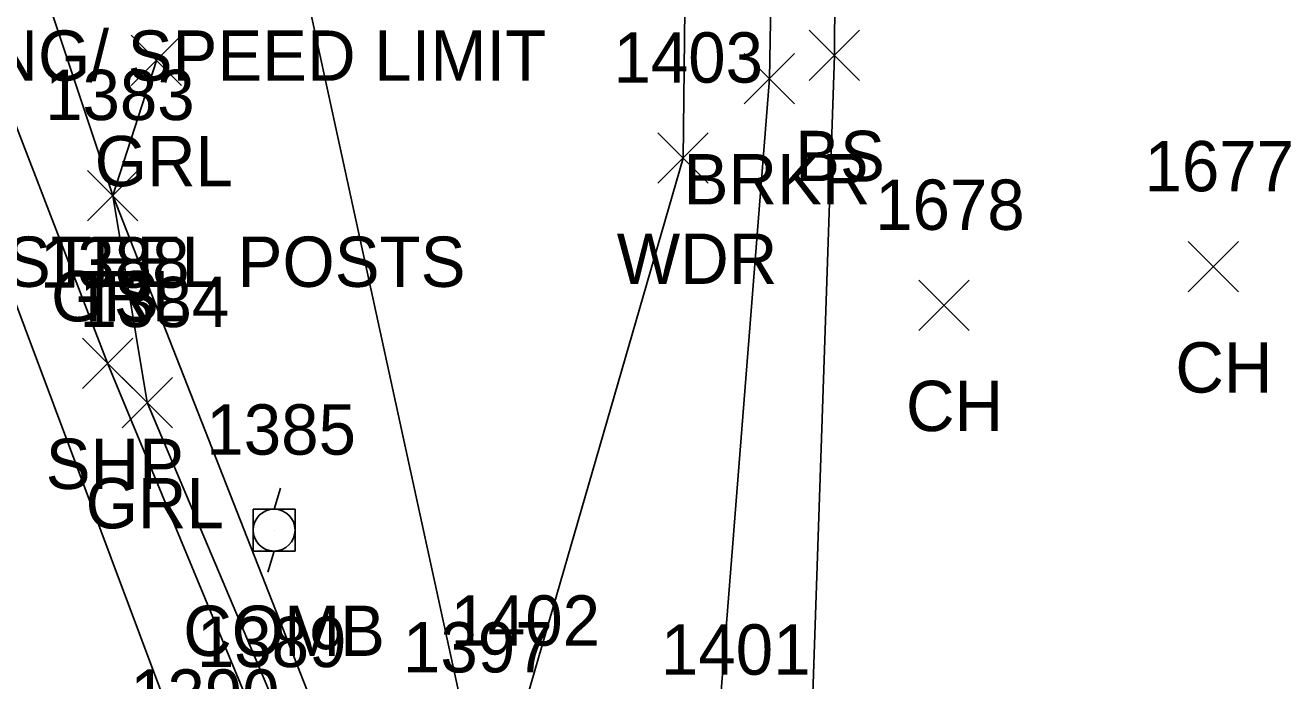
# Model space of a CAD drawing. Extents: x 1651305 to 1654558, y 539481 to 548441.
# Drawn here: x 1654313.4 to 1654363.7, y 544722 to 544748.1 of the extents above; entities that cross this region are included whole.
import ezdxf

# ---------------------------------------------------------------- set-up
doc = ezdxf.new("R2010")
doc.units = 0
for name, color, linetype in [('L_A', 7, 'Continuous'), ('L_I', 7, 'Continuous'), ('L_TIC', 7, 'Continuous'), ('LAWA', 7, 'Continuous'), ('LAWE', 7, 'Continuous'), ('LELB', 7, 'Continuous'), ('P_A', 7, 'Continuous'), ('P_I', 7, 'Continuous'), ('P_TIC', 7, 'Continuous'), ('PET', 7, 'Continuous'), ('PSP', 7, 'Continuous'), ('R_A', 7, 'Continuous'), ('R_C', 7, 'Continuous'), ('R_I', 7, 'Continuous'), ('R_TIC', 7, 'Continuous'), ('RGR', 7, 'Continuous'), ('S_C', 7, 'Continuous'), ('U_A', 7, 'Continuous'), ('U_I', 7, 'Continuous'), ('UP', 7, 'Continuous')]:
    doc.layers.add(name, color=color, linetype=linetype)

msp = doc.modelspace()

# ---------------------------------------------------------------- linework, layer by layer
at = {"layer": 'L_TIC'}
for points in [[(1654344.587, 544745.872), (1654346.587, 544747.872)], [(1654346.587, 544745.872), (1654344.587, 544747.872)], [(1654342.001, 544744.948), (1654344.001, 544746.948)], [(1654344.001, 544744.948), (1654342.001, 544746.948)], [(1654338.568, 544741.787), (1654340.568, 544743.787)], [(1654340.568, 544741.787), (1654338.568, 544743.787)], [(1654315.885, 544740.298), (1654317.885, 544742.298)], [(1654317.885, 544740.298), (1654315.885, 544742.298)], [(1654359.661, 544737.467), (1654361.661, 544739.467)], [(1654361.661, 544737.467), (1654359.661, 544739.467)], [(1654348.946, 544735.935), (1654350.946, 544737.935)], [(1654350.946, 544735.935), (1654348.946, 544737.935)]]:
    msp.add_lwpolyline(points, dxfattribs=at)
at = {"layer": 'LAWA'}
msp.add_lwpolyline([(1654333.089, 544720.406), (1654339.568, 544742.787), (1654339.926, 544774.824), (1654333.777, 544809.516), (1654332.911, 544836.907), (1654333.19, 544866.217)], dxfattribs=at)
at = {"layer": 'LAWE'}
msp.add_lwpolyline([(1654242.515, 544465.967), (1654256.87, 544483.548), (1654283.123, 544539.875), (1654291.834, 544564.241), (1654301.763, 544593.784), (1654310.979, 544627.694), (1654314.699, 544654.654), (1654333.845, 544703.3), (1654340.893, 544719.253), (1654343.001, 544745.948), (1654343.543, 544777.003), (1654341.256, 544814.623), (1654342.705, 544842.641), (1654342.649, 544866.803)], dxfattribs=at)
at = {"layer": 'LELB'}
for points in [[(1654268.864, 544879.178), (1654276.493, 544842.278), (1654286.118, 544815.622), (1654299.147, 544783.593), (1654310.71, 544759.789), (1654316.885, 544741.298), (1654328.163, 544712.614)], [(1654321.982, 544868.568), (1654300.331, 544866.144), (1654280.17, 544869.383), (1654284.965, 544845.051), (1654295.376, 544825.082), (1654318.777, 544790.661), (1654321.652, 544762.863), (1654331.123, 544719.343)], [(1654243.655, 544463.614), (1654257.64, 544478.05), (1654284.349, 544538.419), (1654294.462, 544561.387), (1654312.806, 544626.029), (1654318.85, 544643.272), (1654339.174, 544696.643), (1654344.529, 544715.65), (1654345.587, 544746.872), (1654345.745, 544776.719), (1654344.633, 544815.202), (1654344.44, 544841.842), (1654343.526, 544866.969)]]:
    msp.add_lwpolyline(points, dxfattribs=at)
at = {"layer": 'P_TIC'}
for points in [[(1654315.682, 544733.635), (1654317.682, 544735.635)], [(1654317.682, 544733.635), (1654315.682, 544735.635)]]:
    msp.add_lwpolyline(points, dxfattribs=at)
at = {"layer": 'PET'}
msp.add_lwpolyline([(1654139.13, 545176.501), (1654150.393, 545147.194), (1654157.161, 545131.709), (1654170.764, 545099.134), (1654178.155, 545080.649), (1654186.439, 545060.962), (1654201.827, 545022.365), (1654207.176, 545004.715), (1654219.138, 544973.235), (1654242.36, 544920.072), (1654247.532, 544907.575), (1654259.279, 544878.108), (1654268.455, 544853.759), (1654271.522, 544840.232), (1654282.762, 544813.426), (1654295.449, 544782.265), (1654306.751, 544753.721), (1654320.353, 544717.464), (1654325.712, 544702.64)], dxfattribs=at)
at = {"layer": 'PSP'}
msp.add_lwpolyline([(1654296.828, 544784.807), (1654308.935, 544754.714), (1654316.682, 544734.635), (1654322.93, 544719.555), (1654325.421, 544714.063)], dxfattribs=at)
at = {"layer": 'R_TIC'}
for points in [[(1654317.623, 544745.668), (1654319.623, 544747.668)], [(1654319.623, 544745.668), (1654317.623, 544747.668)], [(1654315.885, 544740.298), (1654317.885, 544742.298)], [(1654317.885, 544740.298), (1654315.885, 544742.298)], [(1654317.26, 544732.069), (1654319.26, 544734.069)], [(1654319.26, 544732.069), (1654317.26, 544734.069)]]:
    msp.add_lwpolyline(points, dxfattribs=at)
at = {"layer": 'RGR'}
msp.add_lwpolyline([(1654318.623, 544746.668), (1654316.885, 544741.298), (1654318.26, 544733.069), (1654327.493, 544711.239)], dxfattribs=at)
at = {"layer": 'UP'}
for p, q in [((1654323.551, 544729.666), (1654323.301, 544728.832)), ((1654322.467, 544727.166), (1654322.467, 544728.832)), ((1654322.467, 544728.832), (1654324.134, 544728.832)), ((1654324.134, 544728.832), (1654324.134, 544727.166)), ((1654323.301, 544727.999), (1654323.301, 544727.999)), ((1654324.134, 544727.166), (1654322.467, 544727.166)), ((1654323.051, 544726.332), (1654323.301, 544727.166))]:
    msp.add_line(p, q, dxfattribs=at)
msp.add_circle((1654323.301, 544727.999), 0.833, dxfattribs=at)

# ---------------------------------------------------------------- texts
at = {"layer": 'L_A'}
for s, p in [('BS', (1654344.028, 544741.872)), ('BRKR', (1654339.591, 544740.948)), ('WDR', (1654336.93, 544737.787)), ('TS', (1654315.295, 544736.298)), ('CH', (1654359.149, 544733.467)), ('CH', (1654348.434, 544731.935))]:
    msp.add_text(s, height=2, dxfattribs=at).set_placement(p)
at = {"layer": 'L_I'}
for s, p in [('1403', (1654336.797, 544745.787)), ('1383', (1654314.193, 544744.298)), ('1677', (1654357.921, 544741.467)), ('1678', (1654347.206, 544739.935)), ('1402', (1654330.317, 544723.406)), ('1397', (1654328.43, 544722.343)), ('1401', (1654338.689, 544722.253))]:
    msp.add_text(s, height=2, dxfattribs=at).set_placement(p)
at = {"layer": 'P_A'}
msp.add_text('SHP', height=2, dxfattribs=at).set_placement((1654314.218, 544729.635))
at = {"layer": 'P_I'}
for s, p in [('1388', (1654313.989, 544737.635)), ('1389', (1654320.229, 544722.555)), ('1390', (1654317.574, 544720.464))]:
    msp.add_text(s, height=2, dxfattribs=at).set_placement(p)
at = {"layer": 'R_A'}
for p in [(1654316.167, 544741.668), (1654314.429, 544736.298), (1654315.804, 544728.069)]:
    msp.add_text('GRL', height=2, dxfattribs=at).set_placement(p)
at = {"layer": 'R_C'}
msp.add_text('SGR W/STEEL POSTS', height=2, dxfattribs=at).set_placement((1654302.828, 544737.668))
at = {"layer": 'R_I'}
for s, p in [('1383', (1654314.193, 544744.298)), ('1384', (1654315.568, 544736.069)), ('1390', (1654317.574, 544720.464))]:
    msp.add_text(s, height=2, dxfattribs=at).set_placement(p)
at = {"layer": 'S_C'}
msp.add_text('BEGIN NO PARKING/ SPEED LIMIT', height=2, dxfattribs=at).set_placement((1654290.133, 544745.861))
at = {"layer": 'U_A'}
msp.add_text('COMB', height=2, dxfattribs=at).set_placement((1654319.686, 544722.999))
at = {"layer": 'U_I'}
msp.add_text('1385', height=2, dxfattribs=at).set_placement((1654320.608, 544730.999))

doc.saveas('drawing.dxf')
